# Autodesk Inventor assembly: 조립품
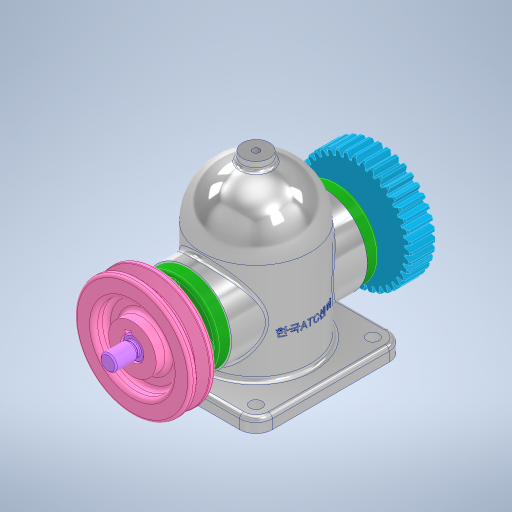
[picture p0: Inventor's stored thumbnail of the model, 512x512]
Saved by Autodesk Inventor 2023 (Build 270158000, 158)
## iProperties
Created: 2025-04
Part Number: 조립품
Document SubType Name: Assembly
Designer: ADMIN_PC
Author: ADMIN_PC
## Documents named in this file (10)
- C:\Users\ADMIN_PC\Desktop\750406V1013\조립품.iam
- C:\Users\ADMIN_PC\Desktop\750406V1013\본체.ipt
- C:\Users\ADMIN_PC\Desktop\750406V1013\750406V1013\깊은 홈 볼 베어링 6203.ipt
- C:\Users\ADMIN_PC\Desktop\750406V1013\750406V1013\축.ipt
- C:\Users\ADMIN_PC\Desktop\750406V1013\750406V1013\커버.ipt
- C:\Users\ADMIN_PC\Desktop\750406V1013\750406V1013\오일 실 26 38 8.ipt
- C:\Users\ADMIN_PC\Desktop\750406V1013\750406V1013\평행 키 5x5x12.ipt
- C:\Users\ADMIN_PC\Desktop\750406V1013\750406V1013\V 벨트 풀리.ipt
- C:\Users\ADMIN_PC\Desktop\750406V1013\750406V1013\칼라.ipt
- C:\Users\ADMIN_PC\Desktop\750406V1013\750406V1013\스퍼기어.ipt
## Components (1 placed, 1 different names)
1. V 벨트 풀리:1
